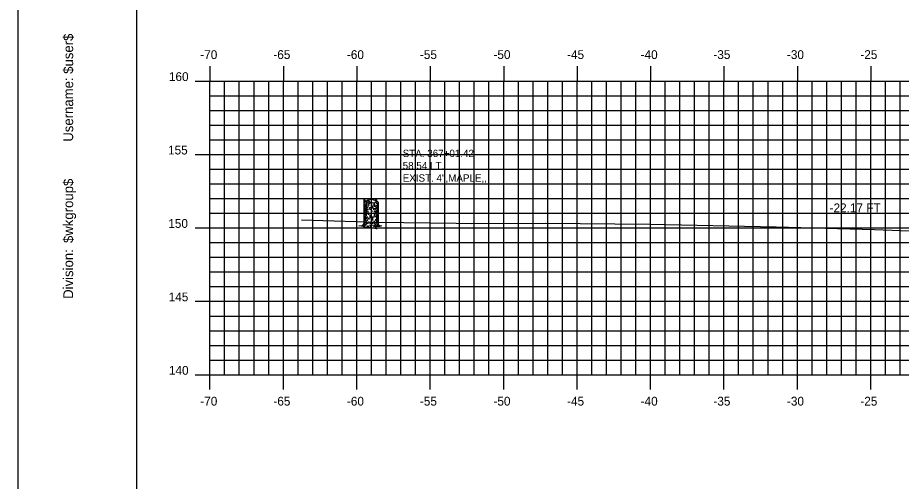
# Model space of a CAD drawing. Extents: x 1147633 to 1147803, y 608981 to 609091.
# Drawn here: x 1147633.4 to 1147693.5, y 609013.1 to 609044.6 of the extents above; entities that cross this region are included whole.
import ezdxf

# ---------------------------------------------------------------- set-up
doc = ezdxf.new("R2010")
doc.units = 0
for name, color, linetype in [('BORDER', 7, 'Continuous'), ('D_Text_Monospaced', 7, 'Continuous'), ('D_Text_Standard', 7, 'Continuous'), ('H_V ANNOTATION', 7, 'Continuous'), ('MAJOR', 7, 'Continuous'), ('MINOR', 7, 'Continuous'), ('PLOT BOUNDARY', 7, 'Continuous'), ('S_Roadway_Centerline', 7, 'Continuous'), ('S_Trees_Decid_NonPay', 7, 'Continuous')]:
    doc.layers.add(name, color=color, linetype=linetype)

msp = doc.modelspace()

# ---------------------------------------------------------------- linework, layer by layer
at = {"layer": 'BORDER'}
msp.add_lwpolyline([(1147641.454, 608984.335), (1147801.454, 608984.335), (1147801.454, 609089.335), (1147641.454, 609089.335)], close=True, dxfattribs=at)
at = {"layer": 'MAJOR'}
for p, q in [((1147646.454, 609041.337), (1147646.454, 609040.335)), ((1147651.454, 609041.337), (1147651.454, 609040.335)), ((1147656.454, 609041.337), (1147656.454, 609040.335)), ((1147661.454, 609041.337), (1147661.454, 609040.335)), ((1147666.454, 609041.337), (1147666.454, 609040.335)), ((1147671.454, 609041.337), (1147671.454, 609040.335)), ((1147676.454, 609041.337), (1147676.454, 609040.335)), ((1147681.454, 609041.337), (1147681.454, 609040.335)), ((1147686.454, 609041.337), (1147686.454, 609040.335)), ((1147691.454, 609041.337), (1147691.454, 609040.335)), ((1147645.452, 609040.335), (1147646.454, 609040.335)), ((1147646.454, 609040.335), (1147786.454, 609040.335)), ((1147646.454, 609020.335), (1147646.454, 609040.335)), ((1147646.454, 609020.335), (1147646.454, 609040.335)), ((1147646.454, 609040.335), (1147786.454, 609040.335)), ((1147651.454, 609020.335), (1147651.454, 609040.335)), ((1147656.454, 609020.335), (1147656.454, 609040.335)), ((1147661.454, 609020.335), (1147661.454, 609040.335)), ((1147666.454, 609020.335), (1147666.454, 609040.335)), ((1147671.454, 609020.335), (1147671.454, 609040.335)), ((1147676.454, 609020.335), (1147676.454, 609040.335)), ((1147681.454, 609020.335), (1147681.454, 609040.335)), ((1147686.454, 609020.335), (1147686.454, 609040.335)), ((1147691.454, 609020.335), (1147691.454, 609040.335)), ((1147645.452, 609035.335), (1147646.454, 609035.335)), ((1147646.454, 609035.335), (1147786.454, 609035.335)), ((1147645.452, 609030.335), (1147646.454, 609030.335)), ((1147646.454, 609030.335), (1147786.454, 609030.335)), ((1147645.452, 609025.335), (1147646.454, 609025.335)), ((1147646.454, 609025.335), (1147786.454, 609025.335)), ((1147645.452, 609020.335), (1147646.454, 609020.335)), ((1147646.454, 609020.335), (1147786.454, 609020.335)), ((1147646.454, 609020.335), (1147786.454, 609020.335)), ((1147646.454, 609019.333), (1147646.454, 609020.335)), ((1147651.454, 609019.333), (1147651.454, 609020.335)), ((1147656.454, 609019.333), (1147656.454, 609020.335)), ((1147661.454, 609019.333), (1147661.454, 609020.335)), ((1147666.454, 609019.333), (1147666.454, 609020.335)), ((1147671.454, 609019.333), (1147671.454, 609020.335)), ((1147676.454, 609019.333), (1147676.454, 609020.335)), ((1147681.454, 609019.333), (1147681.454, 609020.335)), ((1147686.454, 609019.333), (1147686.454, 609020.335)), ((1147691.454, 609019.333), (1147691.454, 609020.335))]:
    msp.add_line(p, q, dxfattribs=at)
at = {"layer": 'MINOR'}
for p, q in [((1147647.454, 609020.335), (1147647.454, 609040.335)), ((1147648.454, 609020.335), (1147648.454, 609040.335)), ((1147649.454, 609020.335), (1147649.454, 609040.335)), ((1147650.454, 609020.335), (1147650.454, 609040.335)), ((1147652.454, 609020.335), (1147652.454, 609040.335)), ((1147653.454, 609020.335), (1147653.454, 609040.335)), ((1147654.454, 609020.335), (1147654.454, 609040.335)), ((1147655.454, 609020.335), (1147655.454, 609040.335)), ((1147657.454, 609020.335), (1147657.454, 609040.335)), ((1147658.454, 609020.335), (1147658.454, 609040.335)), ((1147659.454, 609020.335), (1147659.454, 609040.335)), ((1147660.454, 609020.335), (1147660.454, 609040.335)), ((1147662.454, 609020.335), (1147662.454, 609040.335)), ((1147663.454, 609020.335), (1147663.454, 609040.335)), ((1147664.454, 609020.335), (1147664.454, 609040.335)), ((1147665.454, 609020.335), (1147665.454, 609040.335)), ((1147667.454, 609020.335), (1147667.454, 609040.335)), ((1147668.454, 609020.335), (1147668.454, 609040.335)), ((1147669.454, 609020.335), (1147669.454, 609040.335)), ((1147670.454, 609020.335), (1147670.454, 609040.335)), ((1147672.454, 609020.335), (1147672.454, 609040.335)), ((1147673.454, 609020.335), (1147673.454, 609040.335)), ((1147674.454, 609020.335), (1147674.454, 609040.335)), ((1147675.454, 609020.335), (1147675.454, 609040.335)), ((1147677.454, 609020.335), (1147677.454, 609040.335)), ((1147678.454, 609020.335), (1147678.454, 609040.335)), ((1147679.454, 609020.335), (1147679.454, 609040.335)), ((1147680.454, 609020.335), (1147680.454, 609040.335)), ((1147682.454, 609020.335), (1147682.454, 609040.335)), ((1147683.454, 609020.335), (1147683.454, 609040.335)), ((1147684.454, 609020.335), (1147684.454, 609040.335)), ((1147685.454, 609020.335), (1147685.454, 609040.335)), ((1147687.454, 609020.335), (1147687.454, 609040.335)), ((1147688.454, 609020.335), (1147688.454, 609040.335)), ((1147689.454, 609020.335), (1147689.454, 609040.335)), ((1147690.454, 609020.335), (1147690.454, 609040.335)), ((1147692.454, 609020.335), (1147692.454, 609040.335)), ((1147693.454, 609020.335), (1147693.454, 609040.335)), ((1147646.454, 609039.335), (1147786.454, 609039.335)), ((1147646.454, 609039.335), (1147647.456, 609039.335)), ((1147646.454, 609038.335), (1147786.454, 609038.335)), ((1147646.454, 609038.335), (1147647.456, 609038.335)), ((1147646.454, 609037.335), (1147786.454, 609037.335)), ((1147646.454, 609037.335), (1147647.456, 609037.335)), ((1147646.454, 609036.335), (1147786.454, 609036.335)), ((1147646.454, 609036.335), (1147647.456, 609036.335)), ((1147646.454, 609034.335), (1147786.454, 609034.335)), ((1147646.454, 609034.335), (1147647.456, 609034.335)), ((1147646.454, 609033.335), (1147786.454, 609033.335)), ((1147646.454, 609033.335), (1147647.456, 609033.335)), ((1147646.454, 609032.335), (1147786.454, 609032.335)), ((1147646.454, 609032.335), (1147647.456, 609032.335)), ((1147646.454, 609031.335), (1147786.454, 609031.335)), ((1147646.454, 609031.335), (1147647.456, 609031.335)), ((1147646.454, 609029.335), (1147786.454, 609029.335)), ((1147646.454, 609029.335), (1147647.456, 609029.335)), ((1147646.454, 609028.335), (1147786.454, 609028.335)), ((1147646.454, 609028.335), (1147647.456, 609028.335)), ((1147646.454, 609027.335), (1147786.454, 609027.335)), ((1147646.454, 609027.335), (1147647.456, 609027.335)), ((1147646.454, 609026.335), (1147786.454, 609026.335)), ((1147646.454, 609026.335), (1147647.456, 609026.335)), ((1147646.454, 609024.335), (1147786.454, 609024.335)), ((1147646.454, 609024.335), (1147647.456, 609024.335)), ((1147646.454, 609023.335), (1147786.454, 609023.335)), ((1147646.454, 609023.335), (1147647.456, 609023.335)), ((1147646.454, 609022.335), (1147786.454, 609022.335)), ((1147646.454, 609022.335), (1147647.456, 609022.335)), ((1147646.454, 609021.335), (1147786.454, 609021.335)), ((1147646.454, 609021.335), (1147647.456, 609021.335))]:
    msp.add_line(p, q, dxfattribs=at)
at = {"layer": 'PLOT BOUNDARY'}
msp.add_lwpolyline([(1147633.361, 608981.276), (1147803.361, 608981.276), (1147803.361, 609091.276), (1147633.361, 609091.276)], close=True, dxfattribs=at)
at = {"layer": 'S_Roadway_Centerline'}
msp.add_lwpolyline([(1147652.687, 609030.887), (1147657.892, 609030.723), (1147663.223, 609030.659), (1147664.242, 609030.632), (1147669.27, 609030.646), (1147676.409, 609030.584), (1147685.016, 609030.418), (1147691.706, 609030.233), (1147694.696, 609030.108)], dxfattribs=at)
at = {"layer": 'S_Trees_Decid_NonPay'}
for p, q in [((1147657.013, 609032.207), (1147657.013, 609032.113)), ((1147657.013, 609031.887), (1147657.013, 609031.804)), ((1147657.013, 609031.734), (1147657.013, 609031.483)), ((1147657.081, 609032.121), (1147657.081, 609031.82)), ((1147657.081, 609031.791), (1147657.081, 609031.66)), ((1147657.081, 609031.626), (1147657.081, 609031.345)), ((1147657.2, 609032.138), (1147657.2, 609031.99)), ((1147657.2, 609031.942), (1147657.2, 609031.773)), ((1147657.347, 609032.092), (1147657.347, 609031.985)), ((1147657.347, 609031.757), (1147657.347, 609031.67)), ((1147657.347, 609031.635), (1147657.347, 609031.565)), ((1147657.527, 609031.856), (1147657.527, 609031.656)), ((1147657.644, 609032.039), (1147657.644, 609031.961)), ((1147657.644, 609031.874), (1147657.644, 609031.789)), ((1147657.644, 609031.679), (1147657.644, 609031.578)), ((1147657.731, 609031.856), (1147657.731, 609031.769)), ((1147657.731, 609031.699), (1147657.731, 609031.578)), ((1147657.802, 609032.029), (1147657.802, 609031.977)), ((1147657.802, 609031.874), (1147657.802, 609031.791)), ((1147657.802, 609031.757), (1147657.802, 609031.683)), ((1147657.802, 609031.656), (1147657.802, 609031.596)), ((1147657.802, 609031.543), (1147657.802, 609031.362)), ((1147657.845, 609032.034), (1147657.845, 609031.816)), ((1147657.845, 609031.747), (1147657.845, 609031.596)), ((1147657.871, 609031.964), (1147657.871, 609031.882)), ((1147657.871, 609031.812), (1147657.871, 609031.683)), ((1147657.871, 609031.66), (1147657.871, 609031.478)), ((1147657.013, 609031.4), (1147657.013, 609031.17)), ((1147657.013, 609031.1), (1147657.013, 609030.939)), ((1147657.081, 609031.275), (1147657.081, 609031.131)), ((1147657.081, 609031.06), (1147657.081, 609030.919)), ((1147657.2, 609031.467), (1147657.2, 609031.318)), ((1147657.2, 609031.049), (1147657.2, 609030.896)), ((1147657.347, 609031.232), (1147657.347, 609031.009)), ((1147657.527, 609031.118), (1147657.527, 609030.931)), ((1147657.644, 609031.493), (1147657.644, 609031.417)), ((1147657.644, 609031.232), (1147657.644, 609031.135)), ((1147657.731, 609031.502), (1147657.731, 609031.388)), ((1147657.731, 609031.326), (1147657.731, 609031.244)), ((1147657.731, 609031.158), (1147657.731, 609031.06)), ((1147657.802, 609031.33), (1147657.802, 609031.248)), ((1147657.802, 609031.194), (1147657.802, 609031.024)), ((1147657.802, 609030.99), (1147657.802, 609030.711)), ((1147657.845, 609031.491), (1147657.845, 609031.413)), ((1147657.845, 609031.386), (1147657.845, 609031.279)), ((1147657.845, 609031.244), (1147657.845, 609031.143)), ((1147657.845, 609031.118), (1147657.845, 609030.935)), ((1147657.871, 609031.431), (1147657.871, 609031.184)), ((1147657.871, 609031.165), (1147657.871, 609031.071)), ((1147657.873, 609031.018), (1147657.872, 609030.758)), ((1147657.013, 609030.923), (1147657.013, 609030.818)), ((1147657.013, 609030.781), (1147657.013, 609030.657)), ((1147657.081, 609030.577), (1147657.039, 609030.48)), ((1147657.081, 609030.818), (1147657.081, 609030.637)), ((1147657.2, 609030.684), (1147657.2, 609030.606)), ((1147657.347, 609030.676), (1147657.347, 609030.61)), ((1147657.387, 609030.39), (1147657.352, 609030.536)), ((1147657.527, 609030.9), (1147657.527, 609030.847)), ((1147657.527, 609030.671), (1147657.527, 609030.581)), ((1147657.644, 609030.81), (1147657.644, 609030.585)), ((1147657.731, 609030.931), (1147657.731, 609030.832)), ((1147657.731, 609030.703), (1147657.731, 609030.644)), ((1147657.802, 609030.658), (1147657.802, 609030.633)), ((1147657.843, 609030.593), (1147657.877, 609030.542)), ((1147657.845, 609030.832), (1147657.845, 609030.641)), ((1147657.925, 609030.472), (1147657.857, 609030.503)), ((1147657.871, 609030.719), (1147657.871, 609030.645))]:
    msp.add_line(p, q, dxfattribs=at)
for points in [[(1147657.913, 609032.072), (1147657.913, 609030.66), (1147657.935, 609030.511), (1147658.139, 609030.468), (1147657.999, 609030.433), (1147657.78, 609030.414), (1147657.711, 609030.371), (1147657.832, 609030.282), (1147657.501, 609030.326), (1147657.387, 609030.39), (1147657.295, 609030.33), (1147657.239, 609030.408), (1147657.247, 609030.445), (1147657.186, 609030.447), (1147657.134, 609030.39), (1147656.902, 609030.338), (1147657.029, 609030.427), (1147656.897, 609030.429), (1147656.589, 609030.466), (1147656.828, 609030.497), (1147656.906, 609030.555), (1147656.944, 609030.676), (1147656.961, 609031.03), (1147656.961, 609032.263)], [(1147657.326, 609032.097), (1147657.317, 609032.164), (1147657.293, 609032.169), (1147657.284, 609032.204), (1147657.253, 609032.189), (1147657.239, 609032.204), (1147657.215, 609032.181), (1147657.192, 609032.189), (1147657.179, 609032.238), (1147657.171, 609032.195), (1147657.141, 609032.204), (1147657.137, 609032.152)], [(1147657.818, 609032.152), (1147657.814, 609032.247), (1147657.799, 609032.22), (1147657.799, 609032.341), (1147657.778, 609032.278), (1147657.764, 609032.31), (1147657.747, 609032.255), (1147657.731, 609032.272), (1147657.713, 609032.263), (1147657.694, 609032.196)], [(1147657.795, 609032.028), (1147657.778, 609032.09), (1147657.756, 609032.078), (1147657.725, 609032.113), (1147657.692, 609032.035)], [(1147657.011, 609030.614), (1147657.002, 609030.538), (1147656.924, 609030.488)], [(1147657.536, 609030.532), (1147657.536, 609030.495), (1147657.587, 609030.464), (1147657.604, 609030.414)], [(1147657.647, 609030.538), (1147657.653, 609030.468), (1147657.717, 609030.455)], [(1147657.795, 609030.503), (1147657.751, 609030.538), (1147657.744, 609030.585)], [(1147657.873, 609030.519), (1147657.795, 609030.503), (1147657.778, 609030.459)]]:
    msp.add_lwpolyline(points, dxfattribs=at)
for centre, radius, start, end in [((1147656.98, 609032.263), 0.0179, 152.11676, 168.17229), ((1147656.98, 609032.263), 0.0179, 168.17229, 184.22782), ((1147656.985, 609032.264), 0.0237, 184.22782, 198.17229), ((1147656.995, 609032.267), 0.0336, 198.17229, 216.94859), ((1147656.985, 609032.261), 0.0237, 138.17229, 152.11676), ((1147656.992, 609032.254), 0.0336, 119.39599, 138.17229), ((1147657.043, 609032.303), 0.0935, 216.9486, 228.17229), ((1147657.021, 609032.202), 0.0935, 108.17229, 119.39599), ((1147657.195, 609032.473), 0.322, 228.17229, 250.29024), ((1147657.093, 609031.985), 0.322, 86.05435, 108.17229), ((1147657.932, 609034.53), 2.507, 250.29024, 251.52809), ((1147656.942, 609029.805), 2.507, 78.17229, 86.05435), ((1147656.942, 609029.805), 2.507, 70.29024, 78.17229), ((1147657.679, 609031.862), 0.322, 48.17229, 70.29024), ((1147656.98, 609032.116), 0.0191, 163.94846, 180), ((1147656.98, 609032.116), 0.0191, 180, 196.05154), ((1147656.98, 609031.902), 0.0191, 163.94846, 180), ((1147656.98, 609031.902), 0.0191, 180, 196.05154), ((1147656.98, 609031.799), 0.0191, 163.94846, 180), ((1147656.98, 609031.799), 0.0191, 180, 196.05154), ((1147656.98, 609031.579), 0.0191, 163.94846, 180), ((1147656.98, 609031.579), 0.0191, 180, 196.05154), ((1147656.986, 609032.118), 0.0252, 196.05154, 210), ((1147656.986, 609031.903), 0.0252, 196.05154, 210), ((1147656.986, 609031.801), 0.0252, 196.05154, 210), ((1147656.986, 609031.58), 0.0252, 196.05154, 210), ((1147656.995, 609032.123), 0.0356, 210, 228.74941), ((1147656.995, 609031.909), 0.0356, 210, 228.74941), ((1147656.995, 609031.806), 0.0356, 210, 228.74941), ((1147656.995, 609031.586), 0.0356, 210, 228.74941), ((1147657.036, 609032.17), 0.0984, 228.74941, 240), ((1147657.036, 609031.956), 0.0984, 228.74941, 240), ((1147657.036, 609031.853), 0.0984, 228.74941, 240), ((1147657.036, 609031.633), 0.0984, 228.74941, 240), ((1147657.15, 609032.367), 0.326, 240, 248.32432), ((1147657.15, 609032.153), 0.326, 240, 243.57187), ((1147657.15, 609032.05), 0.326, 240, 243.24303), ((1147657.15, 609031.83), 0.326, 240, 245.15448), ((1147657.15, 609032.254), 0.326, 240.90989, 257.8036), ((1147657.15, 609031.945), 0.326, 245.15448, 257.8036), ((1147657.15, 609032.153), 0.326, 250.41675, 261.8968), ((1147657.15, 609032.05), 0.326, 251.68306, 257.8036), ((1147657.15, 609032.367), 0.326, 257.8036, 261.8968), ((1147657.436, 609034.377), 2.356, 261.8968, 263.27991), ((1147657.436, 609034.163), 2.356, 261.8968, 262.55191), ((1147657.436, 609033.955), 2.356, 263.26817, 265.63617), ((1147657.436, 609034.06), 2.356, 263.34129, 264.99462), ((1147657.436, 609034.264), 2.356, 264.24201, 267.36728), ((1147657.436, 609034.377), 2.356, 265.24001, 267.83857), ((1147657.436, 609034.06), 2.356, 266.50356, 267.83857), ((1147657.932, 609034.53), 2.507, 255.99867, 258.17229), ((1147657.932, 609034.53), 2.507, 258.17229, 264.50134), ((1147657.436, 609034.163), 2.356, 270.81188, 272.1981), ((1147657.436, 609034.06), 2.356, 272.1981, 273.97408), ((1147657.436, 609033.955), 2.356, 273.0067, 275.06467), ((1147657.436, 609034.264), 2.356, 273.14807, 276.77338), ((1147657.436, 609034.163), 2.356, 275.06468, 278.1032), ((1147657.436, 609033.955), 2.356, 277.18685, 278.1032), ((1147657.436, 609034.06), 2.356, 277.38384, 278.1032), ((1147657.723, 609032.153), 0.326, 278.1032, 279.08543), ((1147657.723, 609032.05), 0.326, 278.1032, 284.03823), ((1147657.723, 609031.945), 0.326, 278.1032, 284.03823), ((1147657.781, 609032.35), 0.322, 272.44787, 288.17229), ((1147657.723, 609031.83), 0.326, 284.03823, 300), ((1147657.723, 609032.254), 0.326, 291.95057, 300), ((1147657.723, 609032.153), 0.326, 291.95057, 300), ((1147657.723, 609031.945), 0.326, 291.95057, 300), ((1147657.853, 609032.133), 0.0935, 288.17229, 299.39599), ((1147657.836, 609032.057), 0.0984, 300, 311.25059), ((1147657.836, 609031.956), 0.0984, 300, 311.25059), ((1147657.836, 609031.748), 0.0984, 300, 311.25059), ((1147657.836, 609031.633), 0.0984, 300, 311.25059), ((1147657.832, 609032.032), 0.0935, 36.9486, 48.17229), ((1147657.882, 609032.081), 0.0336, 299.39599, 318.17229), ((1147657.878, 609032.01), 0.0356, 311.25059, 330), ((1147657.878, 609031.909), 0.0356, 311.25059, 330), ((1147657.878, 609031.701), 0.0356, 311.25059, 330), ((1147657.878, 609031.586), 0.0356, 311.25059, 330), ((1147657.879, 609032.068), 0.0336, 18.17229, 36.94859), ((1147657.889, 609032.074), 0.0237, 318.17229, 332.11676), ((1147657.887, 609032.004), 0.0252, 330, 343.94846), ((1147657.887, 609031.903), 0.0252, 330, 343.94846), ((1147657.887, 609031.696), 0.0252, 330, 343.94846), ((1147657.887, 609031.58), 0.0252, 330, 343.94846), ((1147657.895, 609032.072), 0.0179, 332.11676, 348.17229), ((1147657.889, 609032.071), 0.0237, 4.22782, 18.17229), ((1147657.893, 609032.003), 0.0191, 343.94846, 360), ((1147657.893, 609031.902), 0.0191, 343.94846, 360), ((1147657.893, 609031.799), 0.0191, 343.94846, 360), ((1147657.893, 609031.694), 0.0191, 343.94846, 360), ((1147657.893, 609031.579), 0.0191, 343.94846, 360), ((1147657.895, 609032.072), 0.0179, 348.17229, 4.22783), ((1147657.893, 609032.003), 0.0191, 360, 6.11276), ((1147657.893, 609031.902), 0.0191, 360, 6.11276), ((1147657.893, 609031.799), 0.0191, 360, 6.11276), ((1147657.893, 609031.694), 0.0191, 360, 6.11276), ((1147657.893, 609031.579), 0.0191, 360, 6.11276), ((1147656.976, 609030.94), 0.0191, 163.94846, 180), ((1147656.976, 609030.94), 0.0191, 180, 196.05154), ((1147656.978, 609031.364), 0.0191, 163.94846, 180), ((1147656.98, 609031.259), 0.0191, 163.94846, 180), ((1147656.98, 609031.259), 0.0191, 180, 196.05154), ((1147656.981, 609031.464), 0.0191, 163.94846, 180), ((1147656.981, 609031.464), 0.0191, 180, 196.05154), ((1147656.987, 609031.466), 0.0252, 196.05154, 210), ((1147656.986, 609031.261), 0.0252, 196.05154, 210), ((1147656.995, 609031.266), 0.0356, 210, 228.74941), ((1147656.996, 609031.471), 0.0356, 210, 228.74941), ((1147657.036, 609031.313), 0.0984, 228.74941, 240), ((1147657.037, 609031.518), 0.0984, 228.74941, 240), ((1147657.148, 609031.615), 0.326, 240, 256.90786), ((1147657.15, 609031.511), 0.326, 240, 245.15448), ((1147657.151, 609031.716), 0.326, 240, 247.86558), ((1147657.15, 609031.42), 0.326, 241.93896, 253.9183), ((1147657.151, 609031.716), 0.326, 257.66994, 261.8968), ((1147657.437, 609033.726), 2.356, 261.8968, 262.86151), ((1147657.436, 609033.43), 2.356, 262.58433, 264.48651), ((1147657.436, 609033.84), 2.356, 262.65877, 264.79114), ((1147657.436, 609033.317), 2.356, 264.24201, 267.46903), ((1147657.434, 609033.625), 2.356, 264.3443, 266.85288), ((1147657.436, 609033.521), 2.356, 267.83857, 269.00542), ((1147657.436, 609033.84), 2.356, 269.55779, 270), ((1147657.436, 609033.84), 2.356, 270, 272.414), ((1147657.436, 609033.43), 2.356, 272.1981, 275.27259), ((1147657.434, 609033.625), 2.356, 274.97344, 277.24554), ((1147657.436, 609033.84), 2.356, 275.06467, 277.18685), ((1147657.436, 609033.521), 2.356, 275.06467, 276.42799), ((1147657.723, 609031.716), 0.326, 283.90364, 291.80982), ((1147657.723, 609031.511), 0.326, 284.03823, 291.95057), ((1147657.723, 609031.307), 0.326, 284.03823, 291.95057), ((1147657.72, 609031.615), 0.326, 292.40493, 300), ((1147657.723, 609031.716), 0.326, 297.00583, 300), ((1147657.723, 609031.511), 0.326, 297.15252, 300), ((1147657.834, 609031.418), 0.0984, 300, 311.25059), ((1147657.837, 609031.518), 0.0984, 300, 311.25059), ((1147657.836, 609031.313), 0.0984, 300, 311.25059), ((1147657.875, 609031.371), 0.0356, 311.25059, 330), ((1147657.878, 609031.266), 0.0356, 311.25059, 330), ((1147657.879, 609031.471), 0.0356, 311.25059, 330), ((1147657.884, 609031.366), 0.0252, 330, 343.94846), ((1147657.889, 609030.94), 0.0191, 343.94846, 360), ((1147657.889, 609030.94), 0.0191, 360, 6.11276), ((1147657.888, 609031.466), 0.0252, 330, 343.94846), ((1147657.89, 609031.364), 0.0191, 0, 6.11277), ((1147657.89, 609031.364), 0.0191, 343.94846, 360), ((1147657.887, 609031.261), 0.0252, 330, 343.94846), ((1147657.893, 609031.259), 0.0191, 343.94846, 360), ((1147657.893, 609031.464), 0.0191, 0, 6.11277), ((1147657.893, 609031.464), 0.0191, 343.94846, 360), ((1147657.893, 609031.259), 0.0191, 360, 6.11276), ((1147657.893, 609031.169), 0.0191, 360, 6.11276), ((1147656.966, 609030.719), 0.0191, 163.94846, 180), ((1147656.966, 609030.719), 0.0191, 180, 196.05154), ((1147656.971, 609030.721), 0.0252, 196.05154, 210), ((1147656.98, 609030.726), 0.0356, 210, 228.74941), ((1147656.971, 609030.83), 0.0191, 163.94846, 180), ((1147656.971, 609030.83), 0.0191, 180, 196.05154), ((1147656.977, 609030.831), 0.0252, 196.05154, 210), ((1147656.986, 609030.837), 0.0356, 210, 228.74941), ((1147657.022, 609030.774), 0.0984, 228.74941, 240), ((1147656.982, 609030.942), 0.0252, 196.05154, 210), ((1147656.991, 609030.947), 0.0356, 210, 228.74941), ((1147657.027, 609030.884), 0.0984, 228.74941, 240), ((1147657.032, 609030.994), 0.0984, 228.74941, 240), ((1147657.136, 609030.971), 0.326, 240, 247.9161), ((1147657.141, 609031.081), 0.326, 240, 241.90969), ((1147657.146, 609031.192), 0.326, 240, 245.93749), ((1147657.136, 609030.971), 0.326, 260.38342, 261.8968), ((1147657.422, 609032.981), 2.356, 261.8968, 263.53328), ((1147657.432, 609033.202), 2.356, 262.22258, 264.4852), ((1147657.427, 609033.091), 2.356, 264.90887, 266.81578), ((1147657.427, 609033.091), 2.356, 274.18643, 275.28293), ((1147657.422, 609032.981), 2.356, 274.55512, 275.4167), ((1147657.432, 609033.202), 2.356, 277.28629, 278.1032), ((1147657.422, 609032.981), 2.356, 277.54032, 278.1032), ((1147657.708, 609030.971), 0.326, 278.1032, 294.70938), ((1147657.718, 609031.192), 0.326, 278.1032, 284.77414), ((1147657.714, 609031.081), 0.326, 293.6544, 300), ((1147657.822, 609030.774), 0.0984, 300, 311.25059), ((1147657.832, 609030.994), 0.0984, 300, 311.25059), ((1147657.863, 609030.726), 0.0356, 311.25059, 330), ((1147657.872, 609030.721), 0.0252, 330, 343.94846), ((1147657.874, 609030.947), 0.0356, 311.25059, 330), ((1147657.878, 609030.719), 0.0191, 0, 6.11277), ((1147657.878, 609030.719), 0.0191, 343.94846, 360), ((1147657.883, 609030.942), 0.0252, 330, 343.94846)]:
    msp.add_arc(centre, radius, start, end, dxfattribs=at)

# ---------------------------------------------------------------- texts
at = {"layer": 'BORDER'}
for s, p in [('$user$', (1147637.139, 609040.827)), ('Username:', (1147637.139, 609036.203)), ('$wkgroup$', (1147637.139, 609029.305)), ('Division:', (1147637.139, 609025.501))]:
    msp.add_text(s, height=0.6696, rotation=90, dxfattribs=at).set_placement(p)
at = {"layer": 'D_Text_Monospaced'}
for s, height, p in [('STA. 367+01.42', 0.49998, (1147659.579, 609035.158)), ('58.54 LT.', 0.5, (1147659.579, 609034.324)), ('EXIST. 4",MAPLE,,', 0.49998, (1147659.579, 609033.484))]:
    msp.add_text(s, height=height, dxfattribs=at).set_placement(p)
at = {"layer": 'D_Text_Standard'}
msp.add_text('-22.17 FT', height=0.6, dxfattribs=at).set_placement((1147688.647, 609031.399))
at = {"layer": 'H_V ANNOTATION'}
for s, p in [('-70', (1147645.796, 609041.835)), ('-65', (1147650.772, 609041.835)), ('-60', (1147655.78, 609041.835)), ('-55', (1147660.75, 609041.835)), ('-50', (1147665.758, 609041.835)), ('-45', (1147670.772, 609041.835)), ('-40', (1147675.78, 609041.835)), ('-35', (1147680.734, 609041.835)), ('-30', (1147685.742, 609041.835)), ('-25', (1147690.739, 609041.835)), ('160', (1147643.659, 609040.335)), ('155', (1147643.6, 609035.335)), ('150', (1147643.616, 609030.335)), ('145', (1147643.643, 609025.335)), ('140', (1147643.659, 609020.335)), ('-70', (1147645.796, 609018.235)), ('-65', (1147650.772, 609018.235)), ('-60', (1147655.78, 609018.235)), ('-55', (1147660.75, 609018.235)), ('-50', (1147665.758, 609018.235)), ('-45', (1147670.772, 609018.235)), ('-40', (1147675.78, 609018.235)), ('-35', (1147680.734, 609018.235)), ('-30', (1147685.742, 609018.235)), ('-25', (1147690.739, 609018.235))]:
    msp.add_text(s, height=0.6, dxfattribs=at).set_placement(p)
at = {"layer": 'MAJOR'}
msp.add_text('-', height=0.006, dxfattribs=at).set_placement((1147646.45, 609020.335))

doc.saveas('drawing.dxf')
